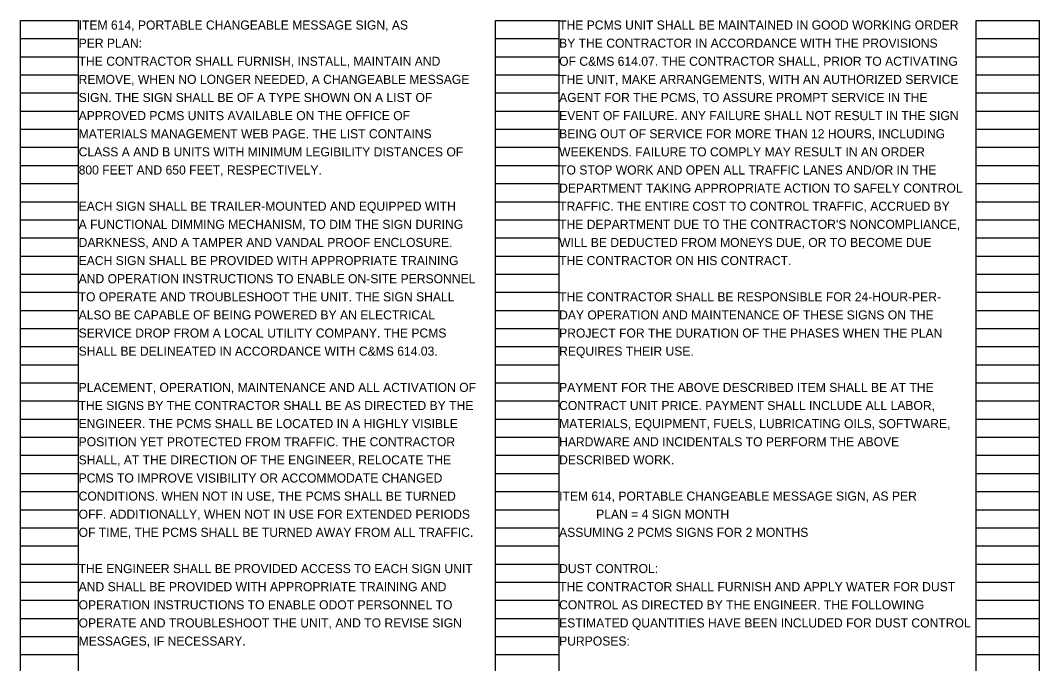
# Model space of a CAD drawing. Extents: x 51924.2 to 51956.2, y 31431.6 to 31530.7.
# Drawn here: x 51925.71 to 51941.45, y 31481.33 to 31491.27 of the extents above; entities that cross this region are included whole.
import ezdxf

# ---------------------------------------------------------------- set-up
doc = ezdxf.new("R2010")
doc.units = 0
doc.layers.add('SH_Data', color=7, linetype='Continuous')
doc.layers.add('SH_Text', color=7, linetype='Continuous')

msp = doc.modelspace()

# ---------------------------------------------------------------- linework, layer by layer
at = {"layer": 'SH_Data'}
for p, q in [((51925.708, 31471.11), (51925.708, 31491.27)), ((51925.708, 31491.27), (51926.608, 31491.27)), ((51926.608, 31471.11), (51926.608, 31491.27)), ((51933.048, 31471.11), (51933.048, 31491.27)), ((51933.048, 31491.27), (51934.028, 31491.27)), ((51934.028, 31471.11), (51934.028, 31491.27)), ((51940.468, 31471.11), (51940.468, 31491.27)), ((51940.468, 31491.27), (51941.448, 31491.27)), ((51941.448, 31471.11), (51941.448, 31491.27)), ((51925.708, 31490.99), (51926.608, 31490.99)), ((51933.048, 31490.99), (51934.028, 31490.99)), ((51940.468, 31490.99), (51941.448, 31490.99)), ((51925.708, 31490.71), (51926.608, 31490.71)), ((51933.048, 31490.71), (51934.028, 31490.71)), ((51940.468, 31490.71), (51941.448, 31490.71)), ((51925.708, 31490.43), (51926.608, 31490.43)), ((51933.048, 31490.43), (51934.028, 31490.43)), ((51940.468, 31490.43), (51941.448, 31490.43)), ((51925.708, 31490.15), (51926.608, 31490.15)), ((51933.048, 31490.15), (51934.028, 31490.15)), ((51940.468, 31490.15), (51941.448, 31490.15)), ((51925.708, 31489.87), (51926.608, 31489.87)), ((51933.048, 31489.87), (51934.028, 31489.87)), ((51940.468, 31489.87), (51941.448, 31489.87)), ((51925.708, 31489.59), (51926.608, 31489.59)), ((51933.048, 31489.59), (51934.028, 31489.59)), ((51940.468, 31489.59), (51941.448, 31489.59)), ((51925.708, 31489.31), (51926.608, 31489.31)), ((51933.048, 31489.31), (51934.028, 31489.31)), ((51940.468, 31489.31), (51941.448, 31489.31)), ((51925.708, 31489.03), (51926.608, 31489.03)), ((51933.048, 31489.03), (51934.028, 31489.03)), ((51940.468, 31489.03), (51941.448, 31489.03)), ((51925.708, 31488.75), (51926.608, 31488.75)), ((51933.048, 31488.75), (51934.028, 31488.75)), ((51940.468, 31488.75), (51941.448, 31488.75)), ((51925.708, 31488.47), (51926.608, 31488.47)), ((51933.048, 31488.47), (51934.028, 31488.47)), ((51940.468, 31488.47), (51941.448, 31488.47)), ((51925.708, 31488.19), (51926.608, 31488.19)), ((51933.048, 31488.19), (51934.028, 31488.19)), ((51940.468, 31488.19), (51941.448, 31488.19)), ((51925.708, 31487.91), (51926.608, 31487.91)), ((51933.048, 31487.91), (51934.028, 31487.91)), ((51940.468, 31487.91), (51941.448, 31487.91)), ((51925.708, 31487.63), (51926.608, 31487.63)), ((51933.048, 31487.63), (51934.028, 31487.63)), ((51940.468, 31487.63), (51941.448, 31487.63)), ((51925.708, 31487.35), (51926.608, 31487.35)), ((51933.048, 31487.35), (51934.028, 31487.35)), ((51940.468, 31487.35), (51941.448, 31487.35)), ((51925.708, 31487.07), (51926.608, 31487.07)), ((51933.048, 31487.07), (51934.028, 31487.07)), ((51940.468, 31487.07), (51941.448, 31487.07)), ((51925.708, 31486.79), (51926.608, 31486.79)), ((51933.048, 31486.79), (51934.028, 31486.79)), ((51940.468, 31486.79), (51941.448, 31486.79)), ((51925.708, 31486.51), (51926.608, 31486.51)), ((51933.048, 31486.51), (51934.028, 31486.51)), ((51940.468, 31486.51), (51941.448, 31486.51)), ((51925.708, 31486.23), (51926.608, 31486.23)), ((51933.048, 31486.23), (51934.028, 31486.23)), ((51940.468, 31486.23), (51941.448, 31486.23)), ((51925.708, 31485.95), (51926.608, 31485.95)), ((51933.048, 31485.95), (51934.028, 31485.95)), ((51940.468, 31485.95), (51941.448, 31485.95)), ((51925.708, 31485.67), (51926.608, 31485.67)), ((51933.048, 31485.67), (51934.028, 31485.67)), ((51940.468, 31485.67), (51941.448, 31485.67)), ((51925.708, 31485.39), (51926.608, 31485.39)), ((51933.048, 31485.39), (51934.028, 31485.39)), ((51940.468, 31485.39), (51941.448, 31485.39)), ((51925.708, 31485.11), (51926.608, 31485.11)), ((51933.048, 31485.11), (51934.028, 31485.11)), ((51940.468, 31485.11), (51941.448, 31485.11)), ((51925.708, 31484.83), (51926.608, 31484.83)), ((51933.048, 31484.83), (51934.028, 31484.83)), ((51940.468, 31484.83), (51941.448, 31484.83)), ((51925.708, 31484.55), (51926.608, 31484.55)), ((51933.048, 31484.55), (51934.028, 31484.55)), ((51940.468, 31484.55), (51941.448, 31484.55)), ((51925.708, 31484.27), (51926.608, 31484.27)), ((51933.048, 31484.27), (51934.028, 31484.27)), ((51940.468, 31484.27), (51941.448, 31484.27)), ((51925.708, 31483.99), (51926.608, 31483.99)), ((51933.048, 31483.99), (51934.028, 31483.99)), ((51940.468, 31483.99), (51941.448, 31483.99)), ((51925.708, 31483.71), (51926.608, 31483.71)), ((51933.048, 31483.71), (51934.028, 31483.71)), ((51940.468, 31483.71), (51941.448, 31483.71)), ((51925.708, 31483.43), (51926.608, 31483.43)), ((51933.048, 31483.43), (51934.028, 31483.43)), ((51940.468, 31483.43), (51941.448, 31483.43)), ((51925.708, 31483.15), (51926.608, 31483.15)), ((51933.048, 31483.15), (51934.028, 31483.15)), ((51940.468, 31483.15), (51941.448, 31483.15)), ((51925.708, 31482.87), (51926.608, 31482.87)), ((51933.048, 31482.87), (51934.028, 31482.87)), ((51940.468, 31482.87), (51941.448, 31482.87)), ((51925.708, 31482.59), (51926.608, 31482.59)), ((51933.048, 31482.59), (51934.028, 31482.59)), ((51940.468, 31482.59), (51941.448, 31482.59)), ((51925.708, 31482.31), (51926.608, 31482.31)), ((51933.048, 31482.31), (51934.028, 31482.31)), ((51940.468, 31482.31), (51941.448, 31482.31)), ((51925.708, 31482.03), (51926.608, 31482.03)), ((51933.048, 31482.03), (51934.028, 31482.03)), ((51940.468, 31482.03), (51941.448, 31482.03)), ((51925.708, 31481.75), (51926.608, 31481.75)), ((51933.048, 31481.75), (51934.028, 31481.75)), ((51940.468, 31481.75), (51941.448, 31481.75)), ((51925.708, 31481.47), (51926.608, 31481.47)), ((51933.048, 31481.47), (51934.028, 31481.47)), ((51940.468, 31481.47), (51941.448, 31481.47))]:
    msp.add_line(p, q, dxfattribs=at)

# ---------------------------------------------------------------- texts
at = {"layer": 'SH_Text'}
for s, p in [('ITEM 614, PORTABLE CHANGEABLE MESSAGE SIGN, AS', (51926.608, 31491.13)), ('THE PCMS UNIT SHALL BE MAINTAINED IN GOOD WORKING ORDER', (51934.028, 31491.13)), ('PER PLAN:', (51926.608, 31490.85)), ('BY THE CONTRACTOR IN ACCORDANCE WITH THE PROVISIONS', (51934.028, 31490.85)), ('THE CONTRACTOR SHALL FURNISH, INSTALL, MAINTAIN AND', (51926.608, 31490.57)), ('OF C&MS 614.07. THE CONTRACTOR SHALL, PRIOR TO ACTIVATING', (51934.028, 31490.57)), ('REMOVE, WHEN NO LONGER NEEDED, A CHANGEABLE MESSAGE', (51926.608, 31490.29)), ('THE UNIT, MAKE ARRANGEMENTS, WITH AN AUTHORIZED SERVICE', (51934.028, 31490.29)), ('SIGN. THE SIGN SHALL BE OF A TYPE SHOWN ON A LIST OF', (51926.608, 31490.01)), ('AGENT FOR THE PCMS, TO ASSURE PROMPT SERVICE IN THE', (51934.028, 31490.01)), ('APPROVED PCMS UNITS AVAILABLE ON THE OFFICE OF', (51926.608, 31489.73)), ('EVENT OF FAILURE. ANY FAILURE SHALL NOT RESULT IN THE SIGN', (51934.028, 31489.73)), ('MATERIALS MANAGEMENT WEB PAGE. THE LIST CONTAINS', (51926.608, 31489.45)), ('BEING OUT OF SERVICE FOR MORE THAN 12 HOURS, INCLUDING', (51934.028, 31489.45)), ('CLASS A AND B UNITS WITH MINIMUM LEGIBILITY DISTANCES OF', (51926.608, 31489.17)), ('WEEKENDS. FAILURE TO COMPLY MAY RESULT IN AN ORDER', (51934.028, 31489.17)), ('800 FEET AND 650 FEET, RESPECTIVELY.', (51926.608, 31488.89)), ('TO STOP WORK AND OPEN ALL TRAFFIC LANES AND/OR IN THE', (51934.028, 31488.89)), ('DEPARTMENT TAKING APPROPRIATE ACTION TO SAFELY CONTROL', (51934.028, 31488.61)), ('EACH SIGN SHALL BE TRAILER-MOUNTED AND EQUIPPED WITH', (51926.608, 31488.33)), ('TRAFFIC. THE ENTIRE COST TO CONTROL TRAFFIC, ACCRUED BY', (51934.028, 31488.33)), ('A FUNCTIONAL DIMMING MECHANISM, TO DIM THE SIGN DURING', (51926.608, 31488.05)), ("THE DEPARTMENT DUE TO THE CONTRACTOR'S NONCOMPLIANCE,", (51934.028, 31488.05)), ('DARKNESS, AND A TAMPER AND VANDAL PROOF ENCLOSURE.', (51926.608, 31487.77)), ('WILL BE DEDUCTED FROM MONEYS DUE, OR TO BECOME DUE', (51934.028, 31487.77)), ('EACH SIGN SHALL BE PROVIDED WITH APPROPRIATE TRAINING', (51926.608, 31487.49)), ('THE CONTRACTOR ON HIS CONTRACT.', (51934.028, 31487.49)), ('AND OPERATION INSTRUCTIONS TO ENABLE ON-SITE PERSONNEL', (51926.608, 31487.21)), ('TO OPERATE AND TROUBLESHOOT THE UNIT. THE SIGN SHALL', (51926.608, 31486.93)), ('THE CONTRACTOR SHALL BE RESPONSIBLE FOR 24-HOUR-PER-', (51934.028, 31486.93)), ('ALSO BE CAPABLE OF BEING POWERED BY AN ELECTRICAL', (51926.608, 31486.65)), ('DAY OPERATION AND MAINTENANCE OF THESE SIGNS ON THE', (51934.028, 31486.65)), ('SERVICE DROP FROM A LOCAL UTILITY COMPANY. THE PCMS', (51926.608, 31486.37)), ('PROJECT FOR THE DURATION OF THE PHASES WHEN THE PLAN', (51934.028, 31486.37)), ('SHALL BE DELINEATED IN ACCORDANCE WITH C&MS 614.03.', (51926.608, 31486.09)), ('REQUIRES THEIR USE.', (51934.028, 31486.09)), ('PLACEMENT, OPERATION, MAINTENANCE AND ALL ACTIVATION OF', (51926.608, 31485.53)), ('PAYMENT FOR THE ABOVE DESCRIBED ITEM SHALL BE AT THE', (51934.028, 31485.53)), ('THE SIGNS BY THE CONTRACTOR SHALL BE AS DIRECTED BY THE', (51926.608, 31485.25)), ('CONTRACT UNIT PRICE. PAYMENT SHALL INCLUDE ALL LABOR,', (51934.028, 31485.25)), ('ENGINEER. THE PCMS SHALL BE LOCATED IN A HIGHLY VISIBLE', (51926.608, 31484.97)), ('MATERIALS, EQUIPMENT, FUELS, LUBRICATING OILS, SOFTWARE,', (51934.028, 31484.97)), ('POSITION YET PROTECTED FROM TRAFFIC. THE CONTRACTOR', (51926.608, 31484.69)), ('HARDWARE AND INCIDENTALS TO PERFORM THE ABOVE', (51934.028, 31484.69)), ('SHALL, AT THE DIRECTION OF THE ENGINEER, RELOCATE THE', (51926.608, 31484.41)), ('DESCRIBED WORK.', (51934.028, 31484.41)), ('PCMS TO IMPROVE VISIBILITY OR ACCOMMODATE CHANGED', (51926.608, 31484.13)), ('CONDITIONS. WHEN NOT IN USE, THE PCMS SHALL BE TURNED', (51926.608, 31483.85)), ('ITEM 614, PORTABLE CHANGEABLE MESSAGE SIGN, AS PER', (51934.028, 31483.85)), ('OFF. ADDITIONALLY, WHEN NOT IN USE FOR EXTENDED PERIODS', (51926.608, 31483.57)), ('           PLAN = 4 SIGN MONTH ', (51934.028, 31483.57)), ('OF TIME, THE PCMS SHALL BE TURNED AWAY FROM ALL TRAFFIC.', (51926.608, 31483.29)), ('ASSUMING 2 PCMS SIGNS FOR 2 MONTHS', (51934.028, 31483.29)), ('THE ENGINEER SHALL BE PROVIDED ACCESS TO EACH SIGN UNIT', (51926.608, 31482.73)), ('DUST CONTROL: ', (51934.028, 31482.73)), ('AND SHALL BE PROVIDED WITH APPROPRIATE TRAINING AND', (51926.608, 31482.45)), ('THE CONTRACTOR SHALL FURNISH AND APPLY WATER FOR DUST ', (51934.028, 31482.45)), ('OPERATION INSTRUCTIONS TO ENABLE ODOT PERSONNEL TO', (51926.608, 31482.17)), ('CONTROL AS DIRECTED BY THE ENGINEER. THE FOLLOWING ', (51934.028, 31482.17)), ('OPERATE AND TROUBLESHOOT THE UNIT, AND TO REVISE SIGN', (51926.608, 31481.89)), ('ESTIMATED QUANTITIES HAVE BEEN INCLUDED FOR DUST CONTROL ', (51934.028, 31481.89)), ('MESSAGES, IF NECESSARY.', (51926.608, 31481.61)), ('PURPOSES: ', (51934.028, 31481.61))]:
    msp.add_text(s, height=0.14, dxfattribs=at).set_placement(p)

doc.saveas('drawing.dxf')
